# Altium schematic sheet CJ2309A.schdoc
size 127 x 101 mm
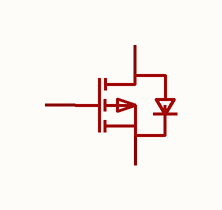
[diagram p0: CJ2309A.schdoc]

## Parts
Q?  cj2309a  [SOT-23-3_L2.9-W1.3-P0.95-LS2.4-BR]  (value not drawn)

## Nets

Not connected (* = marked no-connect by the designer): Q? 1(G) 2(S) 3(D)

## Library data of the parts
Q? = cj2309a: 数量:1个P沟道;漏源电压(Vdss):60V;连续漏极电流(Id):2A;导通电阻(RDS(on)):240mΩ@4.5V;耗散功率(Pd):350mW;阈值电压(Vgs(th)):1.9V;; Manufacturer: CJ(江苏长电/长晶); AddInBom: yes; ModelId: c62791f0466c4ae2a892c056b845b0ca; ModelName: SOT-23-3P_L2.9-W1.3-H1.0-LS2.4-P0.95; ModelTransform: 98.425,114.173,0,180,0,0,0.0005,-0.0005,0; Number: 1个P沟道; Drain to Source Voltage: 60V; Current - Continuous Drain(Id): 2A; Pd - Power Dissipation: 350mW; Gate Threshold Voltage (Vgs(th)): 1.9V; Gate Charge(Qg): 12nC@10V; Input Capacitance(Ciss): 380pF; Reverse Transfer Capacitance (Crss@Vds): 6pF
